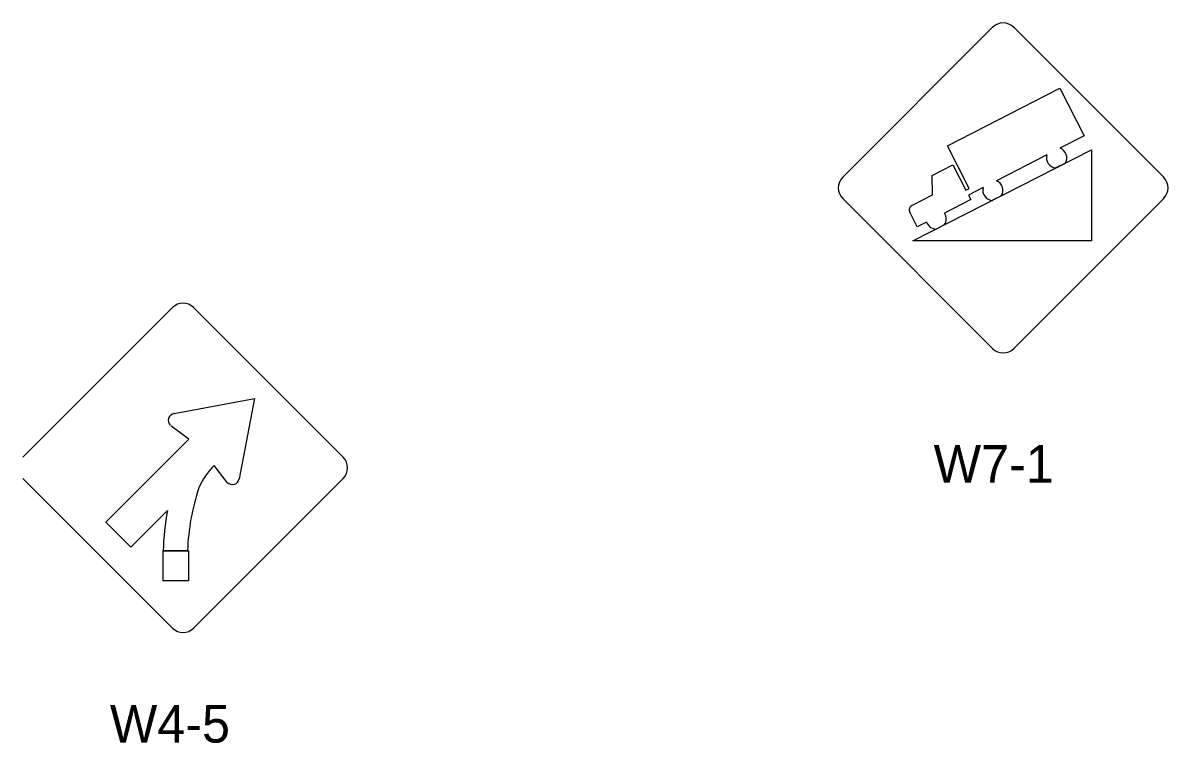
# Model space of a CAD drawing. Extents: x 42133 to 45533, y 41351 to 47951.
# Drawn here: x 44269.2 to 44497.6, y 47180 to 47323.6 of the extents above; entities that cross this region are included whole.
import ezdxf

# ---------------------------------------------------------------- set-up
doc = ezdxf.new("R2010")
doc.units = 0
doc.layers.add('P_TRAF_SIGN_SignDetails', color=7, linetype='Continuous')

msp = doc.modelspace()

# ---------------------------------------------------------------- linework, layer by layer
at = {"layer": 'P_TRAF_SIGN_SignDetails'}
for p, q in [((44462.61, 47322.7), (44432.74, 47292.82)), ((44496.76, 47292.82), (44466.88, 47322.7)), ((44453.61, 47299.11), (44476.06, 47310.58)), ((44476.06, 47310.58), (44480.92, 47301.06)), ((44457.97, 47290.56), (44453.61, 47299.11)), ((44480.92, 47301.06), (44476.07, 47298.58)), ((44446.73, 47280.14), (44482.34, 47298.29)), ((44473.47, 47297.26), (44463.41, 47292.11)), ((44482.34, 47298.29), (44482.34, 47280.14)), ((44450.58, 47293.17), (44454.73, 47295.29)), ((44454.73, 47295.29), (44457.32, 47290.22)), ((44477.14, 47295.64), (44475.27, 47294.69)), ((44450.67, 47289.3), (44450.58, 47293.17)), ((44457.32, 47290.22), (44457.97, 47290.56)), ((44460.74, 47290.76), (44457.82, 47289.26)), ((44432.74, 47288.56), (44462.61, 47258.68)), ((44446.52, 47287.18), (44450.67, 47289.3)), ((44458.27, 47288.37), (44453.02, 47285.69)), ((44457.82, 47289.26), (44458.27, 47288.37)), ((44464.38, 47289.14), (44462.6, 47288.23)), ((44466.88, 47258.68), (44496.76, 47288.56)), ((44447.62, 47282.92), (44446.1, 47285.88)), ((44449.46, 47283.87), (44447.61, 47282.92)), ((44453.05, 47283.36), (44451.36, 47282.5)), ((44482.34, 47280.14), (44446.73, 47280.14)), ((44269.25, 47237.02), (44299.05, 47266.83)), ((44303.3, 47266.83), (44333.11, 47237.02)), ((44299.42, 47245.7), (44315.41, 47248.73)), ((44315.41, 47248.73), (44312.39, 47232.73)), ((44302.31, 47240.58), (44298.77, 47243.27)), ((44285.78, 47224.05), (44302.31, 47240.58)), ((44310.01, 47231.99), (44307.42, 47235.37)), ((44299.05, 47202.97), (44269.25, 47232.78)), ((44333.11, 47232.78), (44303.3, 47202.97)), ((44298.06, 47226.41), (44290.74, 47219.09)), ((44290.74, 47219.09), (44285.78, 47224.05)), ((44302.08, 47218.38), (44297.23, 47218.38))]:
    msp.add_line(p, q, dxfattribs=at)
msp.add_lwpolyline([(44297.23, 47218.38), (44302.25, 47218.38), (44302.25, 47212.37), (44297.23, 47212.37)], close=True, dxfattribs=at)
for centre, radius, start, end in [((44464.74, 47320.56), 3.01, 45, 135), ((44475.41, 47296.68), 2.02, 163.3008, 265.4188), ((44475.41, 47296.68), 2.02, 328.848, 70.641), ((44434.87, 47290.69), 3.01, 135, 225), ((44494.62, 47290.69), 3.01, 315, 45), ((44462.69, 47290.23), 2.02, 165.0333, 268.1701), ((44462.69, 47290.23), 2.02, 326.0564, 69.0151), ((44446.96, 47286.32), 0.966, 117.0928, 207.1027), ((44451.38, 47284.51), 2.02, 323.4222, 35.665), ((44451.38, 47284.51), 2.02, 198.435, 270.7322), ((44301.18, 47264.7), 3.01, 45, 135), ((44301.18, 47264.7), 3.01, 45, 135), ((44464.74, 47260.81), 3.01, 225, 315), ((44299.59, 47244.35), 1.36, 97.2694, 225.9101), ((44316.2, 47226.01), 12.83, 133.1686, 157.6441), ((44330.98, 47234.9), 3.01, 315, 45), ((44347, 47216.76), 44.95, 161.6712, 177.9195), ((44311.01, 47232.98), 1.41, 224.9672, 349.4622), ((44346.98, 47217.3), 49.76, 169.46, 178.7543), ((44301.18, 47205.09), 3.01, 225, 315)]:
    msp.add_arc(centre, radius, start, end, dxfattribs=at)

# ---------------------------------------------------------------- texts
for s, p in [('W7-1', (44450.88, 47231.92)), ('W4-5', (44286.59, 47180.14))]:
    msp.add_text(s, height=7.5, dxfattribs=at).set_placement(p)

doc.saveas('drawing.dxf')
